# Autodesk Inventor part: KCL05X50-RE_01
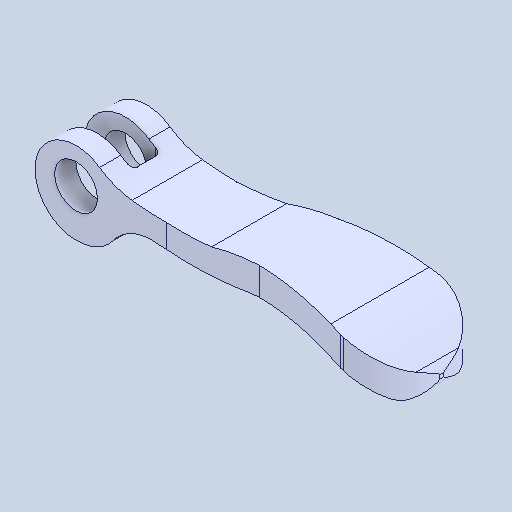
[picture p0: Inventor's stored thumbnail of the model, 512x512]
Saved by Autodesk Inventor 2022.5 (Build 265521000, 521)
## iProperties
Created: 2024-08
Part Number: KCL05X50-RE_01
Material: 一般
Document SubType Name: Modeling
Designer: ImaoCorp
Density: 1 g/cm^3
Appearance: 既定
Author: ImaoCorp
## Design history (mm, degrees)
feature "KCL05X50-RE_01"
node "ソリッド1"
